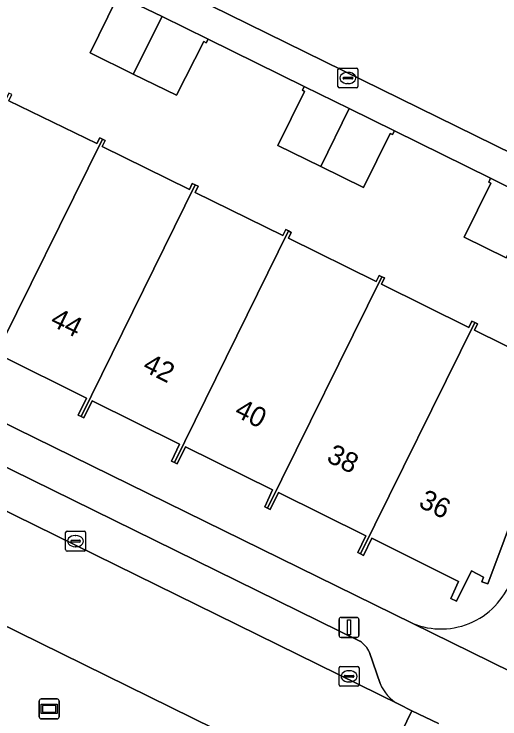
# Model space of a CAD drawing. Extents: x 160349 to 161355, y 381727 to 382854.
# Drawn here: x 160555.04 to 160579.38, y 381959.4 to 381994.7 of the extents above; entities that cross this region are included whole.
import ezdxf

# ---------------------------------------------------------------- set-up
doc = ezdxf.new("R2010")
doc.units = 0
for name, color, linetype in [('IMGEO_Berm_groen', 7, 'Continuous'), ('IMGEO_Erf', 7, 'Continuous'), ('IMGEO_Hek', 7, 'Continuous'), ('IMGEO_Kolk', 7, 'Continuous'), ('IMGEO_Lichtmast', 7, 'Continuous'), ('IMGEO_Pand', 7, 'Continuous'), ('IMGEO_Pand_nummerreeks', 7, 'Continuous'), ('IMGEO_Parkeervlak_open', 7, 'Continuous'), ('IMGEO_Rijbaan_lokaal_open', 7, 'Continuous'), ('IMGEO_Rioolput', 7, 'Continuous'), ('IMGEO_Voetpad_open', 7, 'Continuous'), ('IMGEO_Wegwijzer', 7, 'Continuous')]:
    doc.layers.add(name, color=color, linetype=linetype)

msp = doc.modelspace()

# ---------------------------------------------------------------- linework, layer by layer
at = {"layer": 'IMGEO_Berm_groen'}
msp.add_lwpolyline([(160608.793, 381937.16), (160592.235, 381945.566), (160572.712, 381955.134), (160536.714, 381972.851)], dxfattribs=at)
at = {"layer": 'IMGEO_Erf'}
for points in [[(160582.049, 382019.806), (160567.258, 382027.358), (160569.969, 382032.694), (160568.184, 382033.456), (160568.223, 382033.56), (160567.62, 382033.798), (160563.756, 382026.216), (160561.616, 382027.336), (160561.005, 382026.029), (160561.7, 382025.66), (160561.631, 382025.459), (160561.904, 382025.308), (160561.543, 382019.82), (160560.417, 381999.666), (160555.404, 381999.955), (160555.394, 381999.801), (160586.709, 381984.411), (160587.131, 381985.496), (160591.533, 381996.816)], [(160579.691, 381982.494), (160577.59, 381983.528), (160578.928, 381986.235), (160578.816, 381986.29), (160578.911, 381986.482), (160574.092, 381988.854), (160573.998, 381988.663), (160573.885, 381988.718), (160572.551, 381986.009), (160570.404, 381987.066), (160568.257, 381988.123), (160569.592, 381990.832), (160569.48, 381990.887), (160569.575, 381991.08), (160564.754, 381993.454), (160564.66, 381993.271), (160564.553, 381993.326), (160563.173, 381990.64), (160561.008, 381991.699), (160558.843, 381992.758), (160560.173, 381995.47)], [(160554.78, 381990.359), (160559.185, 381988.213), (160559.333, 381988.508), (160559.466, 381988.442), (160559.599, 381988.375), (160559.449, 381988.064), (160563.824, 381985.921), (160563.967, 381986.218), (160564.116, 381986.147), (160564.265, 381986.075), (160564.114, 381985.766), (160568.504, 381983.616), (160568.657, 381983.909), (160568.79, 381983.839), (160568.923, 381983.769), (160568.78, 381983.47), (160573.176, 381981.3), (160573.331, 381981.613), (160573.462, 381981.548), (160573.594, 381981.483), (160573.444, 381981.168), (160577.822, 381979.008), (160577.974, 381979.321), (160578.114, 381979.253), (160578.254, 381979.185), (160578.111, 381978.874), (160582.404, 381976.755)]]:
    msp.add_lwpolyline(points, dxfattribs=at)
at = {"layer": 'IMGEO_Hek'}
for points in [[(160564.754, 381993.454), (160569.575, 381991.08)], [(160574.092, 381988.854), (160578.911, 381986.482)]]:
    msp.add_lwpolyline(points, dxfattribs=at)
at = {"layer": 'IMGEO_Kolk'}
for p, q in [((160571.262, 381991.075), (160571.262, 381991.927)), ((160571.337, 381992.001), (160572.189, 381992.001)), ((160572.263, 381991.927), (160572.263, 381991.075)), ((160571.521, 381991.495), (160571.521, 381991.507)), ((160571.564, 381991.544), (160571.962, 381991.544)), ((160571.75, 381991.781), (160571.775, 381991.781)), ((160572.005, 381991.507), (160572.005, 381991.495)), ((160571.959, 381991.458), (160571.561, 381991.458)), ((160571.773, 381991.221), (160571.748, 381991.221)), ((160572.189, 381991.001), (160571.337, 381991.001)), ((160571.32, 381961.102), (160571.32, 381961.954)), ((160571.395, 381962.028), (160572.247, 381962.028)), ((160572.321, 381961.954), (160572.321, 381961.102)), ((160571.579, 381961.522), (160571.579, 381961.534)), ((160572.017, 381961.485), (160571.619, 381961.485)), ((160571.622, 381961.571), (160572.02, 381961.571)), ((160571.808, 381961.808), (160571.833, 381961.808)), ((160572.063, 381961.534), (160572.063, 381961.522)), ((160571.831, 381961.248), (160571.806, 381961.248)), ((160572.247, 381961.028), (160571.395, 381961.028))]:
    msp.add_line(p, q, dxfattribs=at)
for points in [[(160571.262, 381991.075), (160571.262, 381991.927)], [(160571.337, 381992.001), (160572.189, 381992.001)], [(160572.263, 381991.927), (160572.263, 381991.075)], [(160572.189, 381991.001), (160571.337, 381991.001)], [(160571.32, 381961.102), (160571.32, 381961.954)], [(160571.395, 381962.028), (160572.247, 381962.028)], [(160572.321, 381961.954), (160572.321, 381961.102)], [(160572.247, 381961.028), (160571.395, 381961.028)]]:
    msp.add_lwpolyline(points, dxfattribs=at)
for centre, radius, start, end in [((160571.339, 381991.925), 0.0765, 91.552, 178.448), ((160571.339, 381991.925), 0.0765, 91.552, 178.448), ((160572.187, 381991.925), 0.0765, 1.552, 88.448), ((160572.187, 381991.925), 0.0765, 1.552, 88.448), ((160571.561, 381991.504), 0.0403, 85.8775, 175.7526), ((160571.558, 381991.494), 0.0366, 178.938, 274.7102), ((160571.962, 381991.501), 0.043, 264.8664, 352.4533), ((160571.966, 381991.506), 0.0386, 1.7309, 96.639), ((160571.339, 381991.077), 0.0765, 181.552, 268.448), ((160571.339, 381991.077), 0.0765, 181.552, 268.448), ((160572.187, 381991.077), 0.0765, 271.552, 358.448), ((160572.187, 381991.077), 0.0765, 271.552, 358.448), ((160571.397, 381961.952), 0.0765, 91.552, 178.448), ((160571.397, 381961.952), 0.0765, 91.552, 178.448), ((160572.245, 381961.952), 0.0765, 1.552, 88.448), ((160572.245, 381961.952), 0.0765, 1.552, 88.448), ((160571.619, 381961.531), 0.0403, 85.8775, 175.7526), ((160571.616, 381961.521), 0.0366, 178.938, 274.7102), ((160572.02, 381961.528), 0.043, 264.8664, 352.4533), ((160572.024, 381961.533), 0.0386, 1.7309, 96.639), ((160571.397, 381961.104), 0.0765, 181.552, 268.448), ((160571.397, 381961.104), 0.0765, 181.552, 268.448), ((160572.245, 381961.104), 0.0765, 271.552, 358.448), ((160572.245, 381961.104), 0.0765, 271.552, 358.448)]:
    msp.add_arc(centre, radius, start, end, dxfattribs=at)
for centre, major_axis, ratio, start_param, end_param in [((160571.749, 381991.501), (-0.387, 0.002), 0.722429, 4.712389, 7.853982), ((160571.774, 381991.501), (-0.39, 0.002), 0.717154, 1.570796, 4.712389), ((160571.807, 381961.528), (-0.387, 0.002), 0.722429, 4.712389, 7.853982), ((160571.832, 381961.528), (-0.39, 0.002), 0.717154, 1.570796, 4.712389)]:
    msp.add_ellipse(centre, major_axis=major_axis, ratio=ratio, start_param=start_param, end_param=end_param, dxfattribs=at)
at = {"layer": 'IMGEO_Lichtmast'}
for p, q in [((160571.32, 381963.578), (160571.32, 381964.378)), ((160571.32, 381964.378), (160571.32, 381963.578)), ((160571.42, 381964.478), (160572.21, 381964.478)), ((160572.21, 381964.478), (160571.42, 381964.478)), ((160572.31, 381964.378), (160572.31, 381963.578)), ((160572.31, 381963.578), (160572.31, 381964.378)), ((160572.21, 381963.478), (160571.42, 381963.478)), ((160571.42, 381963.478), (160572.21, 381963.478))]:
    msp.add_line(p, q, dxfattribs=at)
msp.add_lwpolyline([(160571.74, 381964.353), (160571.89, 381964.353), (160571.89, 381963.603), (160571.74, 381963.603), (160571.74, 381964.353)], dxfattribs=at)
for centre, start, end in [((160571.42, 381964.378), 90, 180), ((160571.42, 381964.378), 90, 180), ((160572.21, 381964.378), 0, 90), ((160572.21, 381964.378), 360, 90), ((160571.42, 381963.578), 180, 270), ((160571.42, 381963.578), 180, 270), ((160572.21, 381963.578), 270, 0), ((160572.21, 381963.578), 270, 0)]:
    msp.add_arc(centre, 0.1, start, end, dxfattribs=at)
at = {"layer": 'IMGEO_Pand'}
for points in [[(160561.008, 381991.699), (160562.455, 381994.581), (160560.155, 381995.707), (160560.065, 381995.522), (160560.173, 381995.47), (160558.843, 381992.758)], [(160561.008, 381991.699), (160563.173, 381990.64), (160564.553, 381993.326), (160564.66, 381993.271), (160564.754, 381993.454), (160562.455, 381994.581)], [(160570.404, 381987.066), (160571.833, 381989.967), (160569.575, 381991.08), (160569.48, 381990.887), (160569.592, 381990.832), (160568.257, 381988.123)], [(160554.778, 381990.745), (160549.069, 381979.148), (160549.21, 381979.081), (160549.622, 381979.912), (160554.003, 381977.762), (160553.589, 381976.918), (160553.731, 381976.849), (160559.466, 381988.442), (160559.333, 381988.508), (160559.185, 381988.213), (160554.78, 381990.359), (160554.927, 381990.676)], [(160570.404, 381987.066), (160572.551, 381986.009), (160573.885, 381988.718), (160573.998, 381988.663), (160574.092, 381988.854), (160571.833, 381989.967)], [(160564.116, 381986.147), (160563.967, 381986.218), (160563.824, 381985.921), (160559.449, 381988.064), (160559.599, 381988.375), (160559.466, 381988.442), (160553.731, 381976.849), (160553.872, 381976.779), (160554.295, 381977.636), (160558.664, 381975.461), (160558.256, 381974.614), (160558.396, 381974.546)], [(160581.163, 381985.37), (160578.911, 381986.482), (160578.816, 381986.29), (160578.928, 381986.235), (160577.59, 381983.528), (160579.691, 381982.494)], [(160563.068, 381972.245), (160568.79, 381983.839), (160568.657, 381983.909), (160568.504, 381983.616), (160564.114, 381985.766), (160564.265, 381986.075), (160564.116, 381986.147), (160558.396, 381974.546), (160558.536, 381974.479), (160558.953, 381975.321), (160563.326, 381973.162), (160562.929, 381972.31)], [(160563.068, 381972.245), (160563.208, 381972.18), (160563.624, 381973.03), (160567.992, 381970.866), (160567.596, 381970.014), (160567.735, 381969.949), (160573.462, 381981.548), (160573.331, 381981.613), (160573.176, 381981.3), (160568.78, 381983.47), (160568.923, 381983.769), (160568.79, 381983.839)], [(160567.735, 381969.949), (160567.874, 381969.885), (160568.293, 381970.735), (160572.662, 381968.573), (160572.254, 381967.726), (160572.398, 381967.657), (160578.114, 381979.253), (160577.974, 381979.321), (160577.822, 381979.008), (160573.444, 381981.168), (160573.594, 381981.483), (160573.462, 381981.548)], [(160578.114, 381979.253), (160572.398, 381967.657), (160572.541, 381967.588), (160572.963, 381968.444), (160577.311, 381966.279), (160576.92, 381965.424), (160577.207, 381965.293), (160577.95, 381966.809), (160578.557, 381966.501), (160578.479, 381966.261), (160578.778, 381966.154), (160582.816, 381976.971), (160582.522, 381977.069), (160582.404, 381976.755), (160578.111, 381978.874), (160578.254, 381979.185)]]:
    msp.add_lwpolyline(points, close=True, dxfattribs=at)
at = {"layer": 'IMGEO_Parkeervlak_open'}
for points in [[(160572.357, 381963.283), (160528.206, 381984.994)], [(160524.716, 381984.511), (160574.307, 381960.126)], [(160573.381, 381961.173), (160572.84, 381962.723)]]:
    msp.add_lwpolyline(points, dxfattribs=at)
for centre, radius, start, end in [((160571.843, 381962.351), 1.064, 20.4392, 61.1163), ((160575.243, 381961.887), 1.994, 200.9742, 242.0069)]:
    msp.add_arc(centre, radius, start, end, dxfattribs=at)
at = {"layer": 'IMGEO_Rijbaan_lokaal_open'}
msp.add_lwpolyline([(160572.712, 381955.134), (160574.957, 381959.806), (160574.307, 381960.126), (160524.716, 381984.511), (160524.448, 381984.643), (160523.423, 381985.137), (160521.176, 381980.499), (160529.706, 381976.301), (160536.714, 381972.851)], close=True, dxfattribs=at)
msp.add_lwpolyline([(160576.306, 381959.157), (160574.957, 381959.806), (160572.712, 381955.134), (160592.235, 381945.566), (160595.361, 381951.949), (160595.167, 381952.06), (160592.923, 381953.139)], dxfattribs=at)
msp.add_arc((160578.756, 381964.577), 5.948, 259.7678, 314.0855, dxfattribs=at)
at = {"layer": 'IMGEO_Rioolput'}
for p, q in [((160557.618, 381967.874), (160557.618, 381968.726)), ((160557.693, 381968.8), (160558.545, 381968.8)), ((160558.106, 381968.58), (160558.131, 381968.58)), ((160558.619, 381968.726), (160558.619, 381967.874)), ((160557.877, 381968.294), (160557.877, 381968.306)), ((160558.315, 381968.257), (160557.917, 381968.257)), ((160557.92, 381968.343), (160558.318, 381968.343)), ((160558.361, 381968.306), (160558.361, 381968.294)), ((160558.129, 381968.02), (160558.104, 381968.02)), ((160558.545, 381967.8), (160557.693, 381967.8))]:
    msp.add_line(p, q, dxfattribs=at)
for points in [[(160557.618, 381967.874), (160557.618, 381968.726)], [(160557.693, 381968.8), (160558.545, 381968.8)], [(160558.619, 381968.726), (160558.619, 381967.874)], [(160558.545, 381967.8), (160557.693, 381967.8)]]:
    msp.add_lwpolyline(points, dxfattribs=at)
for centre, radius, start, end in [((160557.695, 381968.724), 0.0765, 91.552, 178.448), ((160557.695, 381968.724), 0.0765, 91.552, 178.448), ((160558.543, 381968.724), 0.0765, 1.552, 88.448), ((160558.543, 381968.724), 0.0765, 1.552, 88.448), ((160557.917, 381968.303), 0.0403, 85.8775, 175.7526), ((160557.914, 381968.293), 0.0366, 178.938, 274.7102), ((160558.318, 381968.3), 0.043, 264.8664, 352.4533), ((160558.322, 381968.305), 0.0386, 1.7309, 96.639), ((160557.695, 381967.876), 0.0765, 181.552, 268.448), ((160557.695, 381967.876), 0.0765, 181.552, 268.448), ((160558.543, 381967.876), 0.0765, 271.552, 358.448), ((160558.543, 381967.876), 0.0765, 271.552, 358.448)]:
    msp.add_arc(centre, radius, start, end, dxfattribs=at)
for centre, major_axis, ratio, start_param, end_param in [((160558.105, 381968.3), (-0.387, 0.002), 0.722429, 4.712389, 7.853982), ((160558.13, 381968.3), (-0.39, 0.002), 0.717154, 1.570796, 4.712389)]:
    msp.add_ellipse(centre, major_axis=major_axis, ratio=ratio, start_param=start_param, end_param=end_param, dxfattribs=at)
at = {"layer": 'IMGEO_Voetpad_open'}
for points in [[(160555.394, 381999.801), (160555.302, 381998.113), (160555.433, 381998.049), (160560.155, 381995.707), (160562.455, 381994.581), (160564.754, 381993.454), (160569.575, 381991.08), (160571.833, 381989.967), (160574.092, 381988.854), (160578.911, 381986.482), (160581.163, 381985.37)], [(160580.011, 381966.548), (160586.279, 381983.246), (160586.709, 381984.411), (160555.394, 381999.801)], [(160574.983, 381964.188), (160526.761, 381987.863), (160519.2, 381993.627)], [(160526.761, 381987.863), (160574.983, 381964.188)], [(160528.206, 381984.994), (160572.357, 381963.283)], [(160582.816, 381976.971), (160578.778, 381966.154), (160578.479, 381966.261), (160578.557, 381966.501), (160577.95, 381966.809), (160577.207, 381965.293), (160576.92, 381965.424), (160577.311, 381966.279), (160572.963, 381968.444), (160572.541, 381967.588), (160572.398, 381967.657), (160572.254, 381967.726), (160572.662, 381968.573), (160568.293, 381970.735), (160567.874, 381969.885), (160567.735, 381969.949), (160567.596, 381970.014), (160567.992, 381970.866), (160563.624, 381973.03), (160563.208, 381972.18), (160563.068, 381972.245), (160562.929, 381972.31), (160563.326, 381973.162), (160558.953, 381975.321), (160558.536, 381974.479), (160558.396, 381974.546), (160558.256, 381974.614), (160558.664, 381975.461), (160554.295, 381977.636)], [(160582.894, 381960.304), (160574.983, 381964.188)], [(160574.983, 381964.188), (160582.894, 381960.304)], [(160572.84, 381962.723), (160573.381, 381961.173)], [(160574.307, 381960.126), (160574.957, 381959.806), (160576.306, 381959.157)]]:
    msp.add_lwpolyline(points, dxfattribs=at)
for centre, radius, start, end in [((160576.423, 381967.656), 3.755, 247.4526, 342.8355), ((160576.423, 381967.656), 3.755, 247.4526, 342.8355), ((160571.843, 381962.351), 1.064, 20.4392, 61.1163), ((160575.243, 381961.887), 1.994, 200.9742, 242.0069), ((160578.756, 381964.577), 5.948, 259.7678, 314.0855)]:
    msp.add_arc(centre, radius, start, end, dxfattribs=at)
at = {"layer": 'IMGEO_Wegwijzer'}
for p, q in [((160556.303, 381959.495), (160556.303, 381960.295)), ((160556.303, 381960.295), (160556.303, 381959.495)), ((160556.403, 381960.395), (160557.193, 381960.395)), ((160557.193, 381960.395), (160556.403, 381960.395)), ((160557.293, 381960.295), (160557.293, 381959.495)), ((160557.293, 381959.495), (160557.293, 381960.295)), ((160557.193, 381959.395), (160556.403, 381959.395)), ((160556.403, 381959.395), (160557.193, 381959.395))]:
    msp.add_line(p, q, dxfattribs=at)
for points in [[(160556.404, 381960.127), (160557.192, 381960.127), (160557.192, 381959.663), (160556.404, 381959.663), (160556.404, 381960.127)], [(160556.469, 381960.062), (160556.469, 381959.728), (160557.127, 381959.728), (160557.127, 381960.062), (160556.469, 381960.062)]]:
    msp.add_lwpolyline(points, dxfattribs=at)
for centre, start, end in [((160556.403, 381960.295), 90, 180), ((160556.403, 381960.295), 90, 180), ((160557.193, 381960.295), 0, 90), ((160557.193, 381960.295), 360, 90), ((160556.403, 381959.495), 180, 270), ((160556.403, 381959.495), 180, 270), ((160557.193, 381959.495), 270, 0), ((160557.193, 381959.495), 270, 0)]:
    msp.add_arc(centre, 0.1, start, end, dxfattribs=at)

# ---------------------------------------------------------------- texts
at = {"layer": 'IMGEO_Pand_nummerreeks'}
for s, p in [('44', (160556.792, 381979.138)), ('42', (160561.42, 381976.856)), ('40', (160566.023, 381974.587)), ('38', (160570.636, 381972.313)), ('36', (160575.246, 381970.041))]:
    msp.add_text(s, height=1, rotation=333.759, dxfattribs=at).set_placement(p)

doc.saveas('drawing.dxf')
